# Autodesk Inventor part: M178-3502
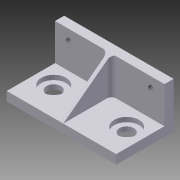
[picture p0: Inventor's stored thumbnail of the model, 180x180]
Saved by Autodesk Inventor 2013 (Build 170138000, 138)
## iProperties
Created: 2004-11
Part Number: M178-3502
Document SubType Name: Modeling
Designer: Autodesk, Inc.
Manufacturer: Standard
Standards Organization: Custom
Material: Aluminium - 6061
Description: SWING ARM MOUNT BRACKET
Mass: 83.1425 g
Surface Area: 128.488 cm^2
Volume: 30.6799 cm^3
Density: 2.71 g/cm^3
CAGE: 1LJX3
Dept. ID: Product Design
Description #2: ---
Finish #1: ---
Finish #2: ---
Material ID: ---
Project Number: ---
Author: Autodesk, Inc.
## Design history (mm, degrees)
sketch "Sketch1"
  geometry: L1 (-20, 6.35)-(20, 6.35); L2 (20, 6.35)-(20, 0); L3 (20, 0)-(-20, 0); L4 (-20, 0)-(-20, 6.35); L5 (20, 0)-(13.65, 0); L6 (13.65, 0)-(13.65, 31.75); L7 (13.65, 31.75)-(20, 31.75); L8 (20, 31.75)-(20, 0); 2 further points
  constraints: 16 end point, 4 parallel, 3 perpendicular, 2 horizontal, 2 midpoint, 1 coincident
  dimensions: "d0" = 40 distance of L2.end L3.end; "d1" = 31.75 distance of L7.end L2.end; "d2" = 6.35 distance of L6.end L7.end
extrude "Extrusion1" new body sketch "Sketch1" stored distance "d3" = 76.2; taper "d4" = 0 deg
feature "Rib1" dims "d5" = 2.54, "d6" = 2.54
sketch "Sketch3"
  geometry: L1 (33.65, -25.4)-(0, -25.4) reference; L2 (33.65, 0)-(33.65, -25.4) reference; L3 (0, 0)-(33.65, 0) reference; L4 (0, 0)-(0, -25.4) reference; L5 (0, -25.4)-(33.65, 0)
  constraints: 2 end point
extrude "Extrusion2" cut sketch "Sketch3" stored distance "d7" = 76.2; taper "d8" = 0 deg
fillet "Fillet1" dims "d9" = 3.175
sketch "Sketch4"
  geometry: L1 (0, 0)-(0, 36.83) reference; L2 (0, 0)-(33.65, 0) reference; 1 further point
  dimensions: "d10" = 20 distance from line of point (20, 12.7) L1; "d11" = 12.7 distance from line of L2 point (20, 12.7)
hole "Hole1" sketch "Sketch4" diameter "d12" = 10.0076; stored, may be unused: countersink angle "d16" = 82 deg, drill point angle "d18" = 118 deg; dims "d13" = 12.7, "d14" = 17.272, "d15" = 3.175, "d17" = 19.05
mirror "Mirror1"
sketch "Sketch5"
  geometry: C1 r 2.54 at (-9.525, 18.1) reference
  constraints: 1 centre point, 1 other
hole "Hole2" sketch "Sketch5" diameter "d19" = 4.1402; stored, may be unused: countersink angle "d23" = 90 deg, drill point angle "d25" = 118 deg; dims "d20" = 12.7, "d21" = 4.3942, "d22" = 5.9944, "d24" = 19.05
mirror "Mirror2"
body "Solid1"
sketch "Sketch2"
  geometry: L1 (-33.65, 0)-(-33.65, 76.2) reference; L2 (0, 76.2)-(0, 0) reference; L3 (0, 38.1)-(-33.65, 38.1)
  constraints: 2 end point, 2 midpoint
node "Projected Loop1"
